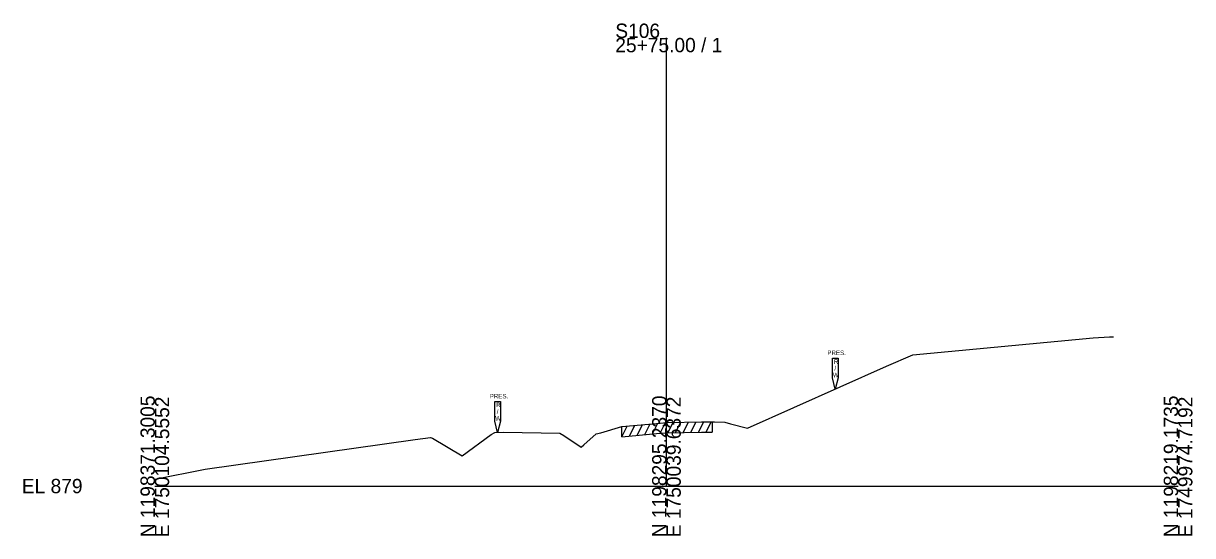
# Model space of a CAD drawing. Extents: x -26 to 1203, y -10 to 19527.
# Drawn here: x -25.7 to 202.8, y 1490.3 to 1590.4 of the extents above; entities that cross this region are included whole.
import ezdxf

# ---------------------------------------------------------------- set-up
doc = ezdxf.new("R2010")
doc.units = 0
for name, color, linetype in [('RD_GPK_XS_Cell', 7, 'Continuous'), ('RD_XS_ExGround', 7, 'Continuous'), ('RD_XS_ExPaveRet', 7, 'Continuous'), ('RD_XS_ExRW', 7, 'Continuous'), ('RD_XS_TX_Elev_EX', 7, 'Continuous')]:
    doc.layers.add(name, color=color, linetype=linetype)

msp = doc.modelspace()

# ---------------------------------------------------------------- linework, layer by layer
at = {"layer": 'RD_GPK_XS_Cell'}
for p, q in [((100, 1500), (100, 1587.6)), ((0, 1500), (100, 1500)), ((100, 1500), (200, 1500))]:
    msp.add_line(p, q, dxfattribs=at)
at = {"layer": 'RD_XS_ExGround'}
msp.add_lwpolyline([(0, 1501.33), (9.85, 1503.29), (50.88, 1509.08), (53.85, 1509.5), (54.28, 1509.37), (60.1, 1505.88), (65.74, 1510.06), (66.46, 1510.47), (68.12, 1510.54), (79.17, 1510.36), (79.91, 1509.9), (83.34, 1507.59), (83.86, 1508.05), (86.26, 1510.18), (87.17, 1510.4), (91.27, 1511.63), (98.05, 1512.25), (100.11, 1512.42), (106.88, 1512.54), (108.94, 1512.55), (109.39, 1512.55), (111.41, 1512.47), (112.5, 1512.14), (115.84, 1511.3), (143.04, 1523.46), (148.16, 1525.67), (183.41, 1528.97), (186.6, 1529.17), (187.38, 1529.2)], dxfattribs=at)
at = {"layer": 'RD_XS_ExPaveRet'}
for p, q in [((91.27, 1509.63), (92.32, 1511.73)), ((91.27, 1509.63), (91.27, 1511.63)), ((92.77, 1509.77), (93.82, 1511.87)), ((94.27, 1509.91), (95.32, 1512)), ((95.77, 1510.05), (96.82, 1512.14)), ((97.27, 1510.18), (98.32, 1512.28)), ((98.77, 1510.31), (99.81, 1512.4)), ((100.27, 1510.42), (101.28, 1512.44)), ((101.77, 1510.45), (102.78, 1512.47)), ((103.27, 1510.47), (104.28, 1512.49)), ((104.77, 1510.5), (105.78, 1512.52)), ((106.27, 1510.52), (107.28, 1512.54)), ((107.77, 1510.54), (108.77, 1512.55)), ((108.94, 1512.55), (108.94, 1510.55)), ((91.27, 1509.63), (98.05, 1510.25)), ((98.05, 1510.25), (100.11, 1510.42)), ((100.11, 1510.42), (106.88, 1510.54)), ((106.88, 1510.54), (108.94, 1510.55))]:
    msp.add_line(p, q, dxfattribs=at)
at = {"layer": 'RD_XS_ExRW'}
for points in [[(132.45, 1524.98), (133.55, 1524.98), (133.55, 1521.16), (133, 1518.97), (132.45, 1521.16)], [(66.45, 1516.51), (67.55, 1516.51), (67.55, 1512.68), (67, 1510.49), (66.45, 1512.68)]]:
    msp.add_lwpolyline(points, close=True, dxfattribs=at)

# ---------------------------------------------------------------- texts
at = {"layer": 'RD_GPK_XS_Cell'}
for s, p in [('S106', (90, 1587.6)), ('25+75.00 / 1', (90, 1584.8)), ('EL 879', (-26, 1498.6))]:
    msp.add_text(s, height=2.8, dxfattribs=at).set_placement(p)
for s, p in [('N 1198371.3005', (0, 1490)), ('N 1198295.2370', (100, 1490)), ('N 1198219.1735', (200, 1490)), ('E 1750104.5552', (2.8, 1490)), ('E 1750039.6372', (102.8, 1490)), ('E 1749974.7192', (202.8, 1490))]:
    msp.add_text(s, height=2.8, rotation=90, dxfattribs=at).set_placement(p)
at = {"layer": 'RD_XS_ExRW'}
for s, p in [('PRES.', (131.45, 1525.61)), ('R', (132.71, 1523.89)), ('W', (132.53, 1521.27)), ('/', (132.83, 1522.58)), ('PRES.', (65.45, 1517.13)), ('R', (66.71, 1515.42)), ('W', (66.53, 1512.79)), ('/', (66.83, 1514.1))]:
    msp.add_text(s, height=0.875, dxfattribs=at).set_placement(p)
at = {"layer": 'RD_XS_TX_Elev_EX'}
msp.add_text('885.21', height=0.0975, rotation=90, dxfattribs=at).set_placement((100.1, 1512.41))

doc.saveas('drawing.dxf')
